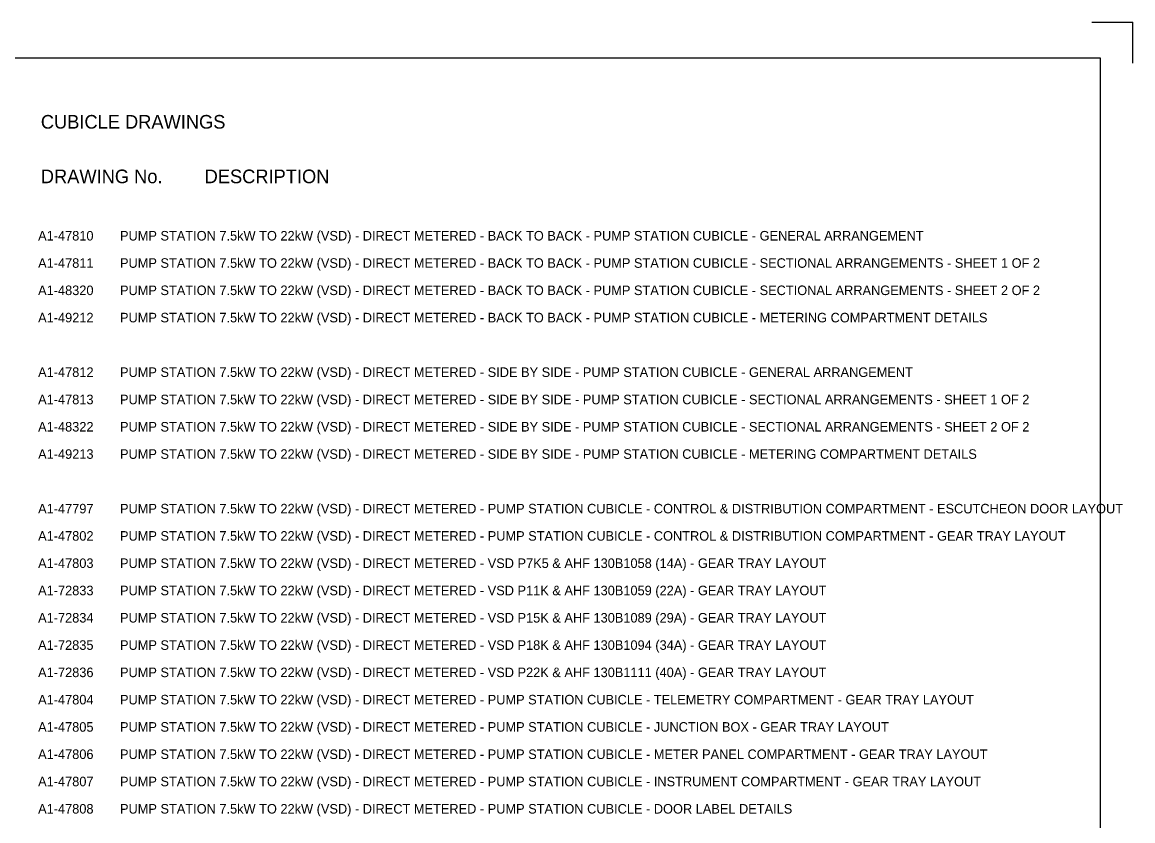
# Model space of a CAD drawing. Extents: x 0 to 841, y 0 to 594.
# Drawn here: x 434.2 to 841, y 301.4 to 594 of the extents above; entities that cross this region are included whole.
import ezdxf

# ---------------------------------------------------------------- set-up
doc = ezdxf.new("R2010")
doc.units = 0
doc.layers.add('A1BORDER', color=7, linetype='Continuous')
doc.layers.add('Level 1', color=7, linetype='Continuous')

msp = doc.modelspace()

# ---------------------------------------------------------------- linework, layer by layer
at = {"layer": 'A1BORDER'}
for p, q in [((826, 594), (841, 594)), ((841, 579), (841, 594)), ((28, 581), (829, 581)), ((829, 581), (829, 15))]:
    msp.add_line(p, q, dxfattribs=at)

# ---------------------------------------------------------------- texts
at = {"layer": 'Level 1'}
for s, height, p in [('CUBICLE DRAWINGS', 5, (441, 555)), ('DRAWING No.', 5, (441, 535)), ('DESCRIPTION', 5, (501, 535)), ('A1-47810', 3.5, (440, 514)), ('PUMP STATION 7.5kW TO 22kW (VSD) - DIRECT METERED - BACK TO BACK - PUMP STATION CUBICLE - GENERAL ARRANGEMENT', 3.49998, (470, 514)), ('A1-47811', 3.5, (440, 504)), ('PUMP STATION 7.5kW TO 22kW (VSD) - DIRECT METERED - BACK TO BACK - PUMP STATION CUBICLE - SECTIONAL ARRANGEMENTS - SHEET 1 OF 2', 3.49998, (470, 504)), ('A1-48320', 3.5, (440, 494)), ('PUMP STATION 7.5kW TO 22kW (VSD) - DIRECT METERED - BACK TO BACK - PUMP STATION CUBICLE - SECTIONAL ARRANGEMENTS - SHEET 2 OF 2', 3.49998, (470, 494)), ('A1-49212', 3.5, (440, 484)), ('PUMP STATION 7.5kW TO 22kW (VSD) - DIRECT METERED - BACK TO BACK - PUMP STATION CUBICLE - METERING COMPARTMENT DETAILS', 3.49998, (470, 484)), ('A1-47812', 3.5, (440, 464)), ('PUMP STATION 7.5kW TO 22kW (VSD) - DIRECT METERED - SIDE BY SIDE - PUMP STATION CUBICLE - GENERAL ARRANGEMENT', 3.49998, (470, 464)), ('A1-47813', 3.5, (440, 454)), ('PUMP STATION 7.5kW TO 22kW (VSD) - DIRECT METERED - SIDE BY SIDE - PUMP STATION CUBICLE - SECTIONAL ARRANGEMENTS - SHEET 1 OF 2', 3.49998, (470, 454)), ('A1-48322', 3.5, (440, 444)), ('PUMP STATION 7.5kW TO 22kW (VSD) - DIRECT METERED - SIDE BY SIDE - PUMP STATION CUBICLE - SECTIONAL ARRANGEMENTS - SHEET 2 OF 2', 3.49998, (470, 444)), ('A1-49213', 3.5, (440, 434)), ('PUMP STATION 7.5kW TO 22kW (VSD) - DIRECT METERED - SIDE BY SIDE - PUMP STATION CUBICLE - METERING COMPARTMENT DETAILS', 3.49998, (470, 434)), ('A1-47797', 3.5, (440, 414)), ('PUMP STATION 7.5kW TO 22kW (VSD) - DIRECT METERED - PUMP STATION CUBICLE - CONTROL & DISTRIBUTION COMPARTMENT - ESCUTCHEON DOOR LAYOUT', 3.49998, (470, 414)), ('A1-47802', 3.5, (440, 404)), ('PUMP STATION 7.5kW TO 22kW (VSD) - DIRECT METERED - PUMP STATION CUBICLE - CONTROL & DISTRIBUTION COMPARTMENT - GEAR TRAY LAYOUT', 3.49998, (470, 404)), ('A1-47803', 3.5, (440, 394)), ('PUMP STATION 7.5kW TO 22kW (VSD) - DIRECT METERED - VSD P7K5 & AHF 130B1058 (14A) - GEAR TRAY LAYOUT', 3.5, (470, 394)), ('A1-72833', 3.5, (440, 384)), ('PUMP STATION 7.5kW TO 22kW (VSD) - DIRECT METERED - VSD P11K & AHF 130B1059 (22A) - GEAR TRAY LAYOUT', 3.5, (470, 384)), ('A1-72834', 3.5, (440, 374)), ('PUMP STATION 7.5kW TO 22kW (VSD) - DIRECT METERED - VSD P15K & AHF 130B1089 (29A) - GEAR TRAY LAYOUT', 3.5, (470, 374)), ('A1-72835', 3.5, (440, 364)), ('PUMP STATION 7.5kW TO 22kW (VSD) - DIRECT METERED - VSD P18K & AHF 130B1094 (34A) - GEAR TRAY LAYOUT', 3.5, (470, 364)), ('A1-72836', 3.5, (440, 354)), ('PUMP STATION 7.5kW TO 22kW (VSD) - DIRECT METERED - VSD P22K & AHF 130B1111 (40A) - GEAR TRAY LAYOUT', 3.5, (470, 354)), ('A1-47804', 3.5, (440, 344)), ('PUMP STATION 7.5kW TO 22kW (VSD) - DIRECT METERED - PUMP STATION CUBICLE - TELEMETRY COMPARTMENT - GEAR TRAY LAYOUT', 3.49998, (470, 344)), ('PUMP STATION 7.5kW TO 22kW (VSD) - DIRECT METERED - PUMP STATION CUBICLE - JUNCTION BOX - GEAR TRAY LAYOUT', 3.49998, (470, 334)), ('A1-47805', 3.5, (440, 334)), ('A1-47806', 3.5, (440, 324)), ('PUMP STATION 7.5kW TO 22kW (VSD) - DIRECT METERED - PUMP STATION CUBICLE - METER PANEL COMPARTMENT - GEAR TRAY LAYOUT', 3.49998, (470, 324)), ('A1-47807', 3.5, (440, 314)), ('PUMP STATION 7.5kW TO 22kW (VSD) - DIRECT METERED - PUMP STATION CUBICLE - INSTRUMENT COMPARTMENT - GEAR TRAY LAYOUT', 3.49998, (470, 314)), ('A1-47808', 3.5, (440, 304)), ('PUMP STATION 7.5kW TO 22kW (VSD) - DIRECT METERED - PUMP STATION CUBICLE - DOOR LABEL DETAILS', 3.5, (470, 304))]:
    msp.add_text(s, height=height, dxfattribs=at).set_placement(p)

doc.saveas('drawing.dxf')
